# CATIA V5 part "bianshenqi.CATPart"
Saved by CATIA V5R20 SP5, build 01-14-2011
Part number: bianshenqi
Material "Emerald": density 2770 kg/m3, Young's modulus 6e+10 Pa, Poisson ratio 0.27, thermal expansion 7e-06 1/K
Material "DS Gold": density 7860 kg/m3, Young's modulus 2e+11 Pa, Poisson ratio 0.266
Material "Amber Mirror": density 2190 kg/m3, Young's modulus 6.5e+10 Pa, Poisson ratio 0.161, thermal expansion 8e-05 1/K
Material "Gold": density 19320 kg/m3, Young's modulus 7.8e+10 Pa, Poisson ratio 0.42, thermal expansion 1.42e-05 1/K
Material "Silver": density 10491 kg/m3, Young's modulus 7.6e+10 Pa, Poisson ratio 0.37, thermal expansion 1.89e-05 1/K
Bounding box of the stored display mesh (mm): x -28.888 to 28.888, y -30 to 30, z -154.641 to 59.803
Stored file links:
  E:\180212218\bianshenqi.CATPart
  C:\Program Files\Dassault Systemes\B20\intel_a\startup\materials\Catalog.CATMaterial
  C:\Program Files\Dassault Systemes\B20\intel_a\startup\materials\black_leather.jpg
  C:\Program Files\Dassault Systemes\B20\intel_a\startup\materials\yellow_env_512x512.jpg
  C:\Program Files\Dassault Systemes\B20\intel_a\startup\materials\malachite.jpg
  C:\Program Files\Dassault Systemes\B20\intel_a\startup\materials\flint.jpg
  C:\Program Files\Dassault Systemes\B20\intel_a\startup\materials\granite.jpg
  C:\Program Files\Dassault Systemes\B20\intel_a\startup\materials\marble_2.jpg
  C:\Program Files\Dassault Systemes\B20\intel_a\startup\materials\sand.jpg
  C:\Program Files\Dassault Systemes\B20\intel_a\startup\materials\bark.jpg
  C:\Program Files\Dassault Systemes\B20\intel_a\startup\materials\teak_2.jpg
  C:\Program Files\Dassault Systemes\B20\intel_a\startup\materials\black_env_512x512.jpg
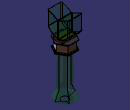
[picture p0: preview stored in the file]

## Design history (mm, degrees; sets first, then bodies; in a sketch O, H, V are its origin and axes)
Body1 (main body), material "Emerald"
  Sketch1 on yz-plane, origin (0, 0, 0), H (0, 1, 0), V (0, 0, 1)
    axis line L1 (0, 60) -> (0, -120)
    point P1 (0, 60)
    line L2 (-30, 17.8517) -> (-30, 59.8767)
    point P3 (-30, 59.8767)
    line L3 (30, 17.8517) -> (30, 60.3303)
    point P4 (30, 60.3303)
    point P5 (0, 46.2221)
    spline S1 through (-30, 59.8767) (-18.0775, 55.7426) (0, 46.2221)
    spline S2 through (0, 46.2221) (19.3383, 55.7426) (30, 60.3303)
    point P6 (0, 34.0373)
    arc A1 centre (0, 34.0373) radius 34.0877 from (-30, 17.8517) to (30, 17.8517) ccw
    point P7 (-30, 17.8517)
    point P8 (30, 17.8517)
    point P9 (30, 17.8517)
    point P10 (-30, 17.8517)
    point P11 (-30, 59.8767)
    point P12 (0, 46.2221)
    point P13 (0, 46.2221)
    point P14 (30, 60.3303)
    distance L2 L1 = 30
    distance L3 L1 = 30
    coincidence: P1 V, P5 L1, P11 P3, P12 P5, P13 P5, P14 P4, P6 L1, P9 P8, P10 P7
    vertical: L1 V, L2 V, L3 V
  Pad1: profile Sketch1, direction (1, 0, 0), length 20, mirrored extent
  Fillet1: radius 3, on edge [start face of Pad1 | face of Pad1 from Sketch1.L2]; edge [face of Pad1 from Sketch1.L2 | end face of Pad1]; edge [start face of Pad1 | face of Pad1 from Sketch1.L3]; edge [face of Pad1 from Sketch1.L3 | end face of Pad1]
  Fillet2: radius 3, on edge [start face of Pad1 | face of Pad1 from Sketch1.A1]
  Body2
    Sketch2 on yz-plane, origin (0, 0, 0), H (0, 1, 0), V (0, 0, 1)
      line L1 (0, 58.1968) -> (-1, 58.1968)
      point P1 (0, 58.1968)
      line L2 (-1, 58.1968) -> (-1, 0)
      point P3 (-1, 0)
      line L3 (-1, 0) -> (1, 0)
      line L4 (1, 0) -> (1, 58.1968)
      point P5 (1, 58.1968)
      line L5 (1, 58.1968) -> (0, 58.1968)
      coincidence: P1 V, P3 H, P5 L1
      horizontal: L1 H, L3 H, L5 H
      vertical: L2 V, L4 V
    Pad2: profile Sketch2, direction (1, 0, 0), length 21, mirrored extent
  Remove1: tool Body2
  Fillet3: radius 1, on edge [face of Pad1 from Sketch1.S1 | end face of Pad1]
  Plane1: type Offset, RefPlane end face of Pad8, Offset 3, reversed
  Sketch3 on Plane1, origin (0, 0, -34.6407), H (1, 0, 0), V (0, 1, 0)
    circle A1 centre (0, 0) radius 20
    radius A1 = 20
  Plane2: type Offset, RefPlane Plane1, Offset 6, reversed
  Sketch4 on Plane2, origin (0, 0, -40.6407), H (1, 0, 0), V (0, 1, 0)
    circle A1 centre (0, 0) radius 17
    radius A1 = 17
  Plane3: type Offset, RefPlane Plane2, Offset 100, reversed
  Sketch5 on Plane3, origin (0, 0, -140.6407), H (1, 0, 0), V (0, 1, 0)
    circle A1 centre (0, 0) radius 24.5
    point P1 (24.5, 0)
    radius A1 = 24.5
    coincidence: A1 P1, P1 H
  Plane4: type Offset, RefPlane Plane3, Offset 7, reversed
  Sketch6 on Plane4, origin (0, 0, -147.6407), H (1, 0, 0), V (0, 1, 0)
    circle A1 centre (0, 0) radius 28
    radius A1 = 28
  Plane5: type Offset, RefPlane Plane4, Offset 5, reversed
  Sketch7 on Plane5, origin (0, 0, -152.6407), H (1, 0, 0), V (0, 1, 0)
    circle A1 centre (0, 0) radius 17.5
    radius A1 = 17.5
  Plane6: type Offset, RefPlane Plane5, Offset 2, reversed
  Sketch8 on Plane6, origin (0, 0, -154.6407), H (1, 0, 0), V (0, 1, 0)
    circle A1 centre (0, 0) radius 10
    radius A1 = 10
  Plane7: type Offset, RefPlane Plane2, Offset 20, reversed
  Plane8: type Offset, RefPlane Plane7, Offset 20, reversed
  Plane9: type Offset, RefPlane Plane8, Offset 20, reversed
  Sketch9 on Plane7, origin (0, 0, -60.6407), H (1, 0, 0), V (0, 1, 0)
    circle A1 centre (0, 0) radius 17
    radius A1 = 17
  Sketch10 on Plane8, origin (0, 0, -80.6407), H (1, 0, 0), V (0, 1, 0)
    circle A1 centre (0, 0) radius 17
    radius A1 = 17
  Sketch11 on Plane9, origin (0, 0, -100.6407), H (1, 0, 0), V (0, 1, 0)
    circle A1 centre (0, 0) radius 17
    radius A1 = 17
  Plane10: type Offset, RefPlane Plane9, Offset 20, reversed
  Sketch12 on Plane10, origin (0, 0, -120.6407), H (1, 0, 0), V (0, 1, 0)
    circle A1 centre (0, 0) radius 17
    radius A1 = 17
  Plane11: type Offset, RefPlane Plane1, Offset 2.8
  Sketch13 on Plane11, origin (0, 0, -31.8407), H (1, 0, 0), V (0, 1, 0)
    circle A1 centre (0, 0) radius 21
    radius A1 = 21
  Loft1: solid, Sections (Sketch13; Sketch3; Sketch4; Sketch9; Sketch10; Sketch11; Sketch12; Sketch5; Sketch6; Sketch7; Sketch8)
  Fillet4: radius 1, on edge [face of Pad1 from Sketch1.S2 | end face of Pad1]
Body3, material "Gold"
  Sketch14 on yz-plane, origin (0, 0, 0), H (0, 1, 0), V (0, 0, 1)
    line L1 (-13.2646, 2.5202) -> (-13.2646, -4.6407)
    point P1 (-13.2646, 2.5202)
    line L2 (12.6572, 2.6711) -> (12.6572, -4.6407)
    point P3 (12.6572, 2.6711)
    spline S1 through (-13.2646, 2.5202) (0, 0) (12.6572, 2.6711)
    line L3 (-13.2646, -4.6407) -> (12.6572, -4.6407)
    point P5 (-13.2646, 2.5202)
    point P6 (0, 0)
    point P7 (12.6572, 2.6711)
    vertical: L1 V, L2 V
    coincidence: P5 P1, P6 O, P7 P3
    horizontal: L3 H
  Pad3: profile Sketch14, direction (1, 0, 0), length 20, mirrored extent
Body4, material "Silver"
  Sketch15 on face of Pad3 from Sketch14.L3, origin (0, 0, -4.6407), H (1, 0, 0), V (0, -1, 0)
    point P1 (14.4439, 25.0176)
    point P2 (-14.4439, 25.0176)
    point P3 (-28.8879, 0)
    point P4 (-14.4439, -25.0176)
    point P5 (14.4439, -25.0176)
    point P6 (28.8879, 0)
    point P7 (0, 25.0176)
    line L1 (14.4439, 25.0176) -> (-14.4439, 25.0176)
    line L2 (-14.4439, 25.0176) -> (-28.8879, 0)
    line L3 (-28.8879, 0) -> (-14.4439, -25.0176)
    line L4 (-14.4439, -25.0176) -> (14.4439, -25.0176)
    line L5 (14.4439, -25.0176) -> (28.8879, 0)
    line L6 (28.8879, 0) -> (14.4439, 25.0176)
    construction line L7 (0, 0) -> (0, 25.0176)
    construction circle A1 centre (0, 0) radius 28.8879
    construction arc A2 centre (14.4439, -25.0176) radius 28.8879 from (-14.4439, -25.0176) to (28.8879, 0) cw
    construction arc A3 centre (-14.4439, 25.0176) radius 28.8879 from (-28.8879, 0) to (14.4439, 25.0176) ccw
    vertical: L7 V
    coincidence: A1 P1, A1 P2, A1 P3, A1 P4, A1 P5, A1 P6, A2 O, A3 O
    midpoint: P7 L1
    parallelism: L1 L4
  Pad4: profile Sketch15, direction (0, 0, -1), length 2
  Fillet5: radius 1, on edge [face of Pad4 from Sketch15.L5 | end face of Pad4]; edge [face of Pad4 from Sketch15.L6 | end face of Pad4]; edge [face of Pad4 from Sketch15.L1 | end face of Pad4]; edge [face of Pad4 from Sketch15.L2 | end face of Pad4]; edge [face of Pad4 from Sketch15.L3 | end face of Pad4]; edge [face of Pad4 from Sketch15.L4 | end face of Pad4]
Body5, material "DS Gold"
  Sketch16 on end face of Pad4, origin (0, 0, -6.6407), H (1, 0, 0), V (0, -1, 0)
    point P1 (13.3418, 23.1086)
    point P2 (-13.3418, 23.1086)
    point P3 (-26.6835, 0)
    point P4 (-13.3418, -23.1086)
    point P5 (13.3418, -23.1086)
    point P6 (26.6835, 0)
    point P7 (0, 23.1086)
    line L1 (13.3418, 23.1086) -> (-13.3418, 23.1086)
    line L2 (-13.3418, 23.1086) -> (-26.6835, 0)
    line L3 (-26.6835, 0) -> (-13.3418, -23.1086)
    line L4 (-13.3418, -23.1086) -> (13.3418, -23.1086)
    line L5 (13.3418, -23.1086) -> (26.6835, 0)
    line L6 (26.6835, 0) -> (13.3418, 23.1086)
    construction line L7 (0, 0) -> (0, 23.1086)
    construction circle A1 centre (0, 0) radius 26.6835
    construction arc A2 centre (13.3418, -23.1086) radius 26.6835 from (-13.3418, -23.1086) to (26.6835, 0) cw
    construction arc A3 centre (-13.3418, 23.1086) radius 26.6835 from (-26.6835, 0) to (13.3418, 23.1086) ccw
    vertical: L7 V
    coincidence: A1 P1, A1 P2, A1 P3, A1 P4, A1 P5, A1 P6, A2 O, A3 O
    midpoint: P7 L1
    parallelism: L1 L4
  Pad5: profile Sketch16, direction (0, 0, -1), length 1.5
Body6, material "Amber Mirror"
  Sketch17 on end face of Pad5, origin (0, 0, -8.1407), H (1, 0, 0), V (0, -1, 0)
    point P1 (12.2308, 21.1843)
    point P2 (-12.2308, 21.1843)
    point P3 (-24.4616, 0)
    point P4 (-12.2308, -21.1843)
    point P5 (12.2308, -21.1843)
    point P6 (24.4616, 0)
    point P7 (0, 21.1843)
    line L1 (12.2308, 21.1843) -> (-12.2308, 21.1843)
    line L2 (-12.2308, 21.1843) -> (-24.4616, 0)
    line L3 (-24.4616, 0) -> (-12.2308, -21.1843)
    line L4 (-12.2308, -21.1843) -> (12.2308, -21.1843)
    line L5 (12.2308, -21.1843) -> (24.4616, 0)
    line L6 (24.4616, 0) -> (12.2308, 21.1843)
    construction line L7 (0, 0) -> (0, 21.1843)
    construction circle A1 centre (0, 0) radius 24.4616
    construction arc A2 centre (12.2308, -21.1843) radius 24.4616 from (-12.2308, -21.1843) to (24.4616, 0) cw
    construction arc A3 centre (-12.2308, 21.1843) radius 24.4616 from (-24.4616, 0) to (12.2308, 21.1843) ccw
    vertical: L7 V
    coincidence: A1 P1, A1 P2, A1 P3, A1 P4, A1 P5, A1 P6, A2 O, A3 O
    midpoint: P7 L1
    parallelism: L1 L4
  Pad6: profile Sketch17, direction (0, 0, -1), length 20
  Sketch18 on end face of Pad6, origin (0, 0, -28.1407), H (1, 0, 0), V (0, -1, 0)
    point P1 (13.3418, 23.1086)
    point P2 (-13.3418, 23.1086)
    point P3 (-26.6835, 0)
    point P4 (-13.3418, -23.1086)
    point P5 (13.3418, -23.1086)
    point P6 (26.6835, 0)
    point P7 (0, 23.1086)
    line L1 (13.3418, 23.1086) -> (-13.3418, 23.1086)
    line L2 (-13.3418, 23.1086) -> (-26.6835, 0)
    line L3 (-26.6835, 0) -> (-13.3418, -23.1086)
    line L4 (-13.3418, -23.1086) -> (13.3418, -23.1086)
    line L5 (13.3418, -23.1086) -> (26.6835, 0)
    line L6 (26.6835, 0) -> (13.3418, 23.1086)
    construction line L7 (0, 0) -> (0, 23.1086)
    construction circle A1 centre (0, 0) radius 26.6835
    construction arc A2 centre (13.3418, -23.1086) radius 26.6835 from (-13.3418, -23.1086) to (26.6835, 0) cw
    construction arc A3 centre (-13.3418, 23.1086) radius 26.6835 from (-26.6835, 0) to (13.3418, 23.1086) ccw
    vertical: L7 V
    coincidence: A1 P1, A1 P2, A1 P3, A1 P4, A1 P5, A1 P6, A2 O, A3 O
    midpoint: P7 L1
    parallelism: L1 L4
  Pad7: profile Sketch18, direction (0, 0, -1), length 1.5
  Sketch19 on end face of Pad7, origin (0, 0, -29.6407), H (1, 0, 0), V (0, -1, 0)
    point P1 (14.4439, 25.0176)
    point P2 (-14.4439, 25.0176)
    point P3 (-28.8879, 0)
    point P4 (-14.4439, -25.0176)
    point P5 (14.4439, -25.0176)
    point P6 (28.8879, 0)
    point P7 (0, 25.0176)
    line L1 (14.4439, 25.0176) -> (-14.4439, 25.0176)
    line L2 (-14.4439, 25.0176) -> (-28.8879, 0)
    line L3 (-28.8879, 0) -> (-14.4439, -25.0176)
    line L4 (-14.4439, -25.0176) -> (14.4439, -25.0176)
    line L5 (14.4439, -25.0176) -> (28.8879, 0)
    line L6 (28.8879, 0) -> (14.4439, 25.0176)
    construction line L7 (0, 0) -> (0, 25.0176)
    construction circle A1 centre (0, 0) radius 28.8879
    construction arc A2 centre (14.4439, -25.0176) radius 28.8879 from (-14.4439, -25.0176) to (28.8879, 0) cw
    construction arc A3 centre (-14.4439, 25.0176) radius 28.8879 from (-28.8879, 0) to (14.4439, 25.0176) ccw
    vertical: L7 V
    coincidence: A1 P1, A1 P2, A1 P3, A1 P4, A1 P5, A1 P6, A2 O, A3 O
    midpoint: P7 L1
    parallelism: L1 L4
  Pad8: profile Sketch19, direction (0, 0, -1), length 2
  Fillet6: radius 1, on face of Pad8 from Sketch19.L2; edge [face of Pad8 from Sketch19.L3 | end face of Pad8]; face of Pad8 from Sketch19.L1; edge [face of Pad8 from Sketch19.L4 | end face of Pad8]; edge [face of Pad8 from Sketch19.L5 | end face of Pad8]; edge [face of Pad8 from Sketch19.L6 | end face of Pad8]
  Fillet7: radius 1, on edge [start face of Pad7 | face of Pad7 from Sketch18.L3]; edge [start face of Pad7 | face of Pad7 from Sketch18.L2]; edge [start face of Pad7 | face of Pad7 from Sketch18.L4]; edge [start face of Pad7 | face of Pad7 from Sketch18.L5]; edge [start face of Pad7 | face of Pad7 from Sketch18.L6]; edge [start face of Pad7 | face of Pad7 from Sketch18.L1]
